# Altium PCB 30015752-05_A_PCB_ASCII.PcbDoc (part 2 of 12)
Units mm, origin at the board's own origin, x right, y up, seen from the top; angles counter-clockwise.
Board outline 100.05 x 72 mm, 10 copper layers (Top, GND_2, Signal_3, Signal_4, PWR_5, GND_6, Signal_7, Signal_8, GND_9, Bottom), stack 1.493 mm thick; 577 components, 546 nets, 2389 pads, 1412 vias.
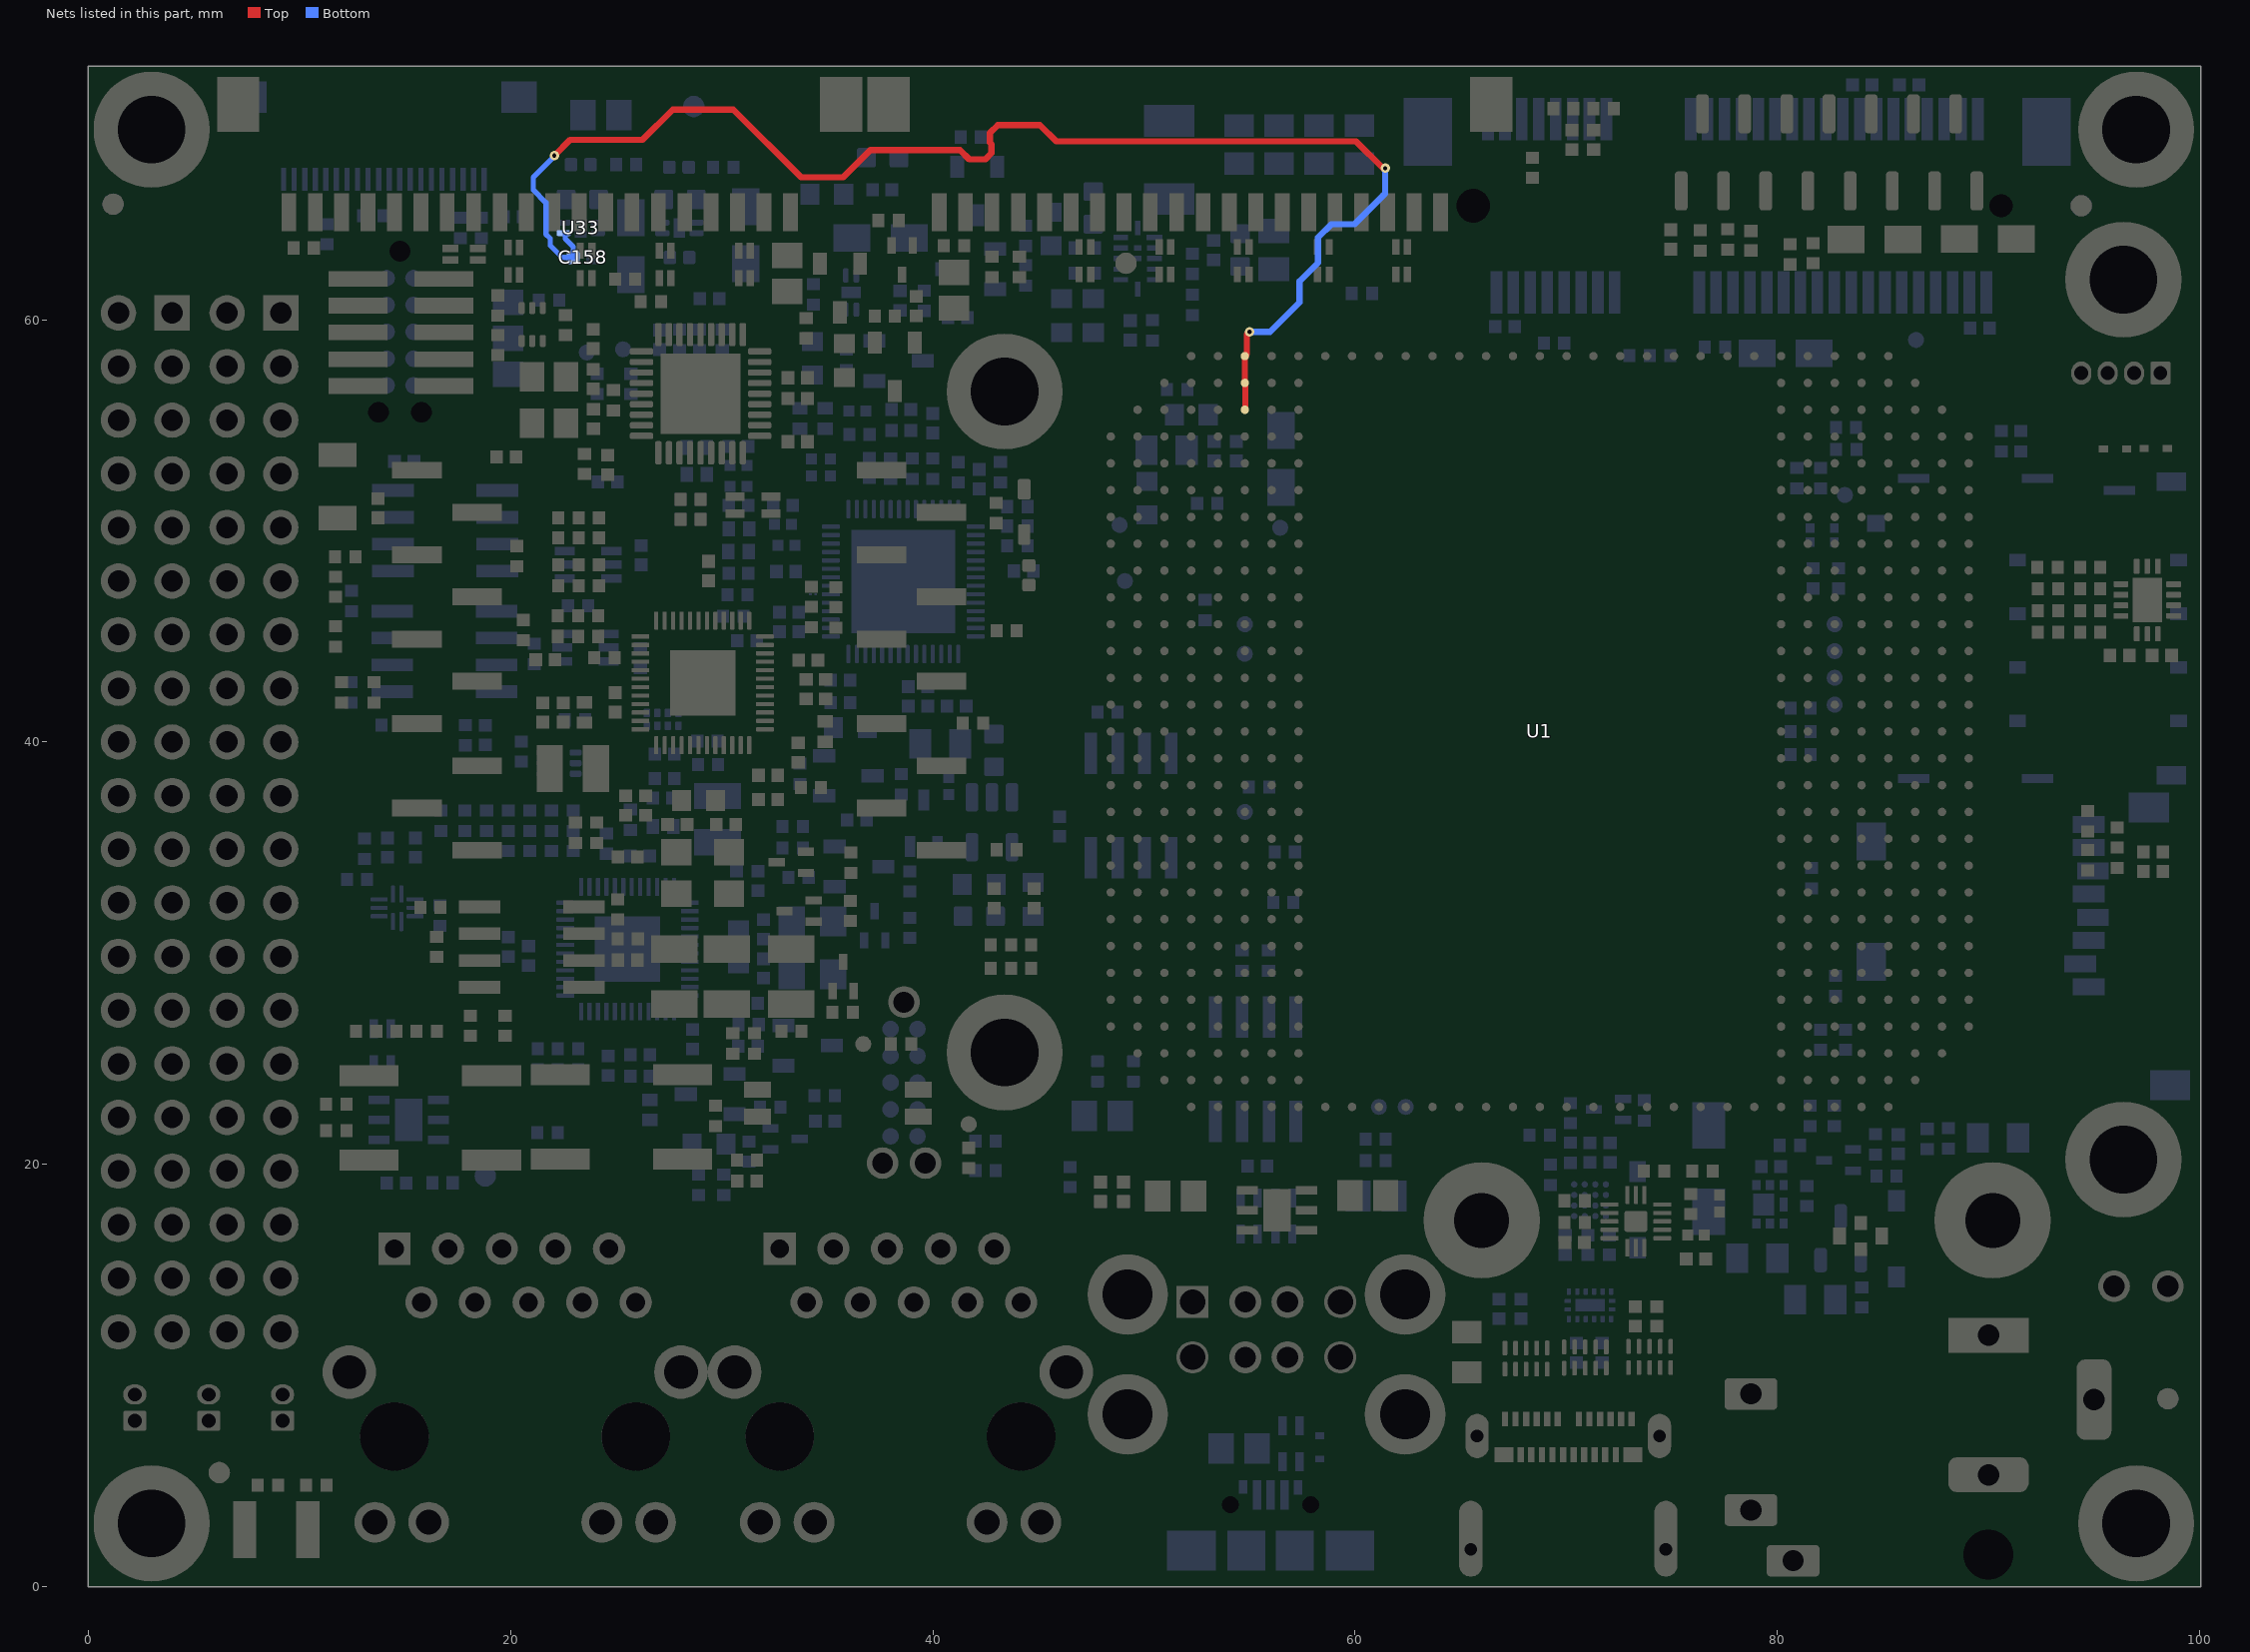
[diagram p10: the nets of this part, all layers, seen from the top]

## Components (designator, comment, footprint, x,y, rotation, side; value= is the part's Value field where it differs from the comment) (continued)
R56 "0" RESC1005X40N#1 96.1,34.52 r270 top
R57 "0" RESC1005X40N#1 96.1,35.48 r90 top
R58 "100" RESC1005X40N#1 77.05,58.7 r0 bottom
R59 "1.0K" RESC1005X40N#1 19.74,26.56 r90 top
R60 "120" RESC1005X40N#1 16.5,30.3 r270 top
R61 "1.0K" RESC1005X40N#1 12.459,46.681 r270 bottom
R62 "120" RESC1005X40N#1 14.375,40.8 r0 bottom
R63 "120" RESC1005X40N#1 12.175,48.775 r180 top
R64 "100" RESC1005X40N#1 87.1,21.2 r90 bottom
R65 "0" RESC1005X40N#1 13.075,34.95 r270 bottom
R66 "0" RESC1005X40N#1 12.725,33.5 r0 bottom
R67 "0" RESC1005X40N#1 16.7,36.275 r270 bottom
R68 "0" RESC1005X40N#1 16.65,31.775 r90 bottom
R69 "100K" RESC1005X40N#1 31.3,20.6 r90 bottom
R70 "10.0K" RESC1005X40N#1 32.3,22.7 r0 bottom
R71 "0" RESC1609X55N 29.4,20.95 r180 bottom
R72 "1.0K" RESC1005X40N#1 33.365,34.992 r0 bottom
R73 "1.0K" RESC1005X40N#1 33.365,35.992 r0 bottom
R74 "10.0K" RESC1005X40N#1 33.64,33.592 r0 bottom
R75 "10.0K" RESC1005X40N#1 24.54,35.192 r90 bottom
R76 "0" RESC1005X40N#1 13.525,42.35 r90 top
R77 "0" RESC1005X40N#1 12,42.35 r90 top
R78 "0" RESC1005X40N#1 11.75,21.6 r180 top
R79 "0" RESC1005X40N#1 11.75,22.85 r180 top
R80 "10.0K" RESC1005X40N#1 24.2,39 r270 bottom
R81 "4.7K" RESC1005X40N#1 25.675,36.325 r270 bottom
R82 "2.37K" RESC1005X40N#1 31.275,26.625 r180 bottom
R83 "150" RESC1005X40N#1 28.9,19.025 r90 bottom
R84 "150" RESC1005X40N#1 10.8,4.8 r180 top
R85 "0" RESC3225X60N 8.9,2.7 r0 top
R86 "10.0K" RESC1005X40N#1 20.915,36.272 r90 bottom
R87 "10.0K" RESC1005X40N#1 20.915,35.312 r90 bottom
R88 "10.0K" RESC1005X40N#1 19.89,36.272 r90 bottom
R89 "10.0K" RESC1005X40N#1 19.89,35.312 r90 bottom
R90 "10.0K" RESC1005X40N#1 21.76,24.475 r180 bottom
R91 "10.0K" RESC1005X40N#1 22.72,24.475 r180 bottom
R92 "10.0K" RESC1005X40N#1 21.94,36.272 r90 bottom
R93 "10.0K" RESC1005X40N#1 21.94,35.312 r90 bottom
R94 "10.0K" RESC1005X40N#1 18.865,36.272 r90 bottom
R95 "10.0K" RESC1005X40N#1 18.865,35.312 r90 bottom
R96 "10.0K" RESC1005X40N#1 22.965,36.272 r90 bottom
R97 "10.0K" RESC1005X40N#1 22.965,35.312 r90 bottom
R98 "10.0K" RESC1005X40N#1 17.84,36.272 r90 bottom
R99 "10.0K" RESC1005X40N#1 17.84,35.312 r90 bottom
R100 "10.0K" RESC1005X40N#1 21.76,25.475 r180 bottom
R101 "10.0K" RESC1005X40N#1 22.72,25.475 r180 bottom
R102 "12K" RESC1609X55N 30.8,30.3 r90 bottom
R103 "12K" RESC1609X55N 28.9,37.225 r180 top
R104 "1.0K" RESC1005X40N#1 24.075,35.7 r270 top
R105 "1.0K" RESC1005X40N#1 23.075,35.7 r270 top
R106 "10.0K" RESC1005X40N#1 29.35,38.925 r0 bottom
R107 "10.0K" RESC1005X40N#1 24.45,44 r180 top
R108 "100K" RESC1005X40N#1 36.12,34.28 r90 top
R109 "100K" RESC1005X40N#1 36.1,32 r90 top
R110 "22" RESC1005X40N#1 94.825,45.2 r180 top
R111 "22" RESC1005X40N#1 94.825,46.225 r180 top
R112 "49.9" RESC1005X40N#1 92.8,48.275 r0 top
R113 "4.7K" RESC1005X40N#1 23.05,41.05 r180 bottom
R114 "2.37K" RESC1005X40N#1 34.225,37.85 r180 top
R115 "150" RESC1005X40N#1 46.5,19.4 r90 bottom
R116 "150" RESC1005X40N#1 30.1,19.025 r90 bottom
R117 "49.9" RESC1005X40N#1 92.825,46.225 r180 top
R118 "10.0K" RESC1005X40N#1 22.745,47.4 r180 top
R119 "10.0K" RESC1005X40N#1 23.705,47.4 r180 top
R120 "10.0K" RESC1005X40N#1 22.745,48.4 r180 top
R121 "10.0K" RESC1005X40N#1 23.705,48.4 r180 top
R122 "10.0K" RESC1005X40N#1 35.4,46.855 r90 top
R123 "10.0K" RESC1005X40N#1 35.4,45.895 r90 top
R124 "10.0K" RESC1005X40N#1 22.72,45.975 r180 top
R125 "10.0K" RESC1005X40N#1 23.68,45.975 r180 top
R126 "10.0K" RESC1005X40N#1 22.745,49.675 r180 top
R127 "10.0K" RESC1005X40N#1 23.705,49.675 r180 top
R128 "10.0K" RESC1005X40N#1 22.72,45 r180 top
R129 "10.0K" RESC1005X40N#1 23.68,45 r180 top
R130 "10.0K" RESC1005X40N#1 22.745,50.625 r180 top
R131 "10.0K" RESC1005X40N#1 23.705,50.625 r180 top
R132 "10.0K" RESC1005X40N#1 34.25,46.88 r90 top
R133 "10.0K" RESC1005X40N#1 34.25,45.92 r90 top
R134 "10.0K" RESC1005X40N#1 10.2,63.4 r180 top
R135 "1M_1%" RESC1005X40N#1 24.869,56.191 r270 top
R136 "47K" RESC1005X40N#1 25.425,61.925 r0 top
R137 "10.0K" RESC1005X40N#1 26.65,60.85 r180 top
R138 "47K" RESC1005X40N#1 30.025,59.05 r90 bottom
R139 "47K" RESC1005X40N#1 28.95,59.05 r90 bottom
R140 "47K" RESC1005X40N#1 28,59.05 r90 bottom
R141 "12.1k" RESC1005X40N#1 23.5,53.175 r90 top
R142 "10.0K" RESC1005X40N#1 54.65,29.65 r90 bottom
R143 "10.0K" RESC1005X40N#1 55.9,29.65 r90 bottom
R144 "100K" RESC1005X40N#1 37.9,64.7 r0 top
R145 "10.0K" RESC1005X40N#1 37.725,60.175 r0 top
R146 "0" RESC1609X55N 35.809,58.069 r270 top
R147 "10.0K" RESC1005X40N#1 70.4,18.275 r0 top
R148 "10.0K" RESC1005X40N#1 70.4,17.25 r0 top
R149 "47K" RESC1005X40N#1 69.25,19.5 r90 bottom
R150 "52.3k" RESC1005X40N#1 68.75,21.375 r0 bottom
R151 "1.0K" RESC1005X40N#1 70.205,20.55 r270 bottom
R152 "22.1K" RESC1005X40N#1 70.2,22.425 r270 bottom
R153 "100K" RESC1005X40N#1 73.7,22.55 r90 bottom
R154 "10.0K" RESC1005X40N#1 43.2,52.78 r270 bottom
R155 "0" RESC1005X40N#1 44,50.225 r180 bottom
R156 "0" RESC1005X40N#1 44,49.3 r180 bottom
R157 "0" RESC1005X40N#1 41.2,52.775 r270 bottom
R158 "0" RESC1005X40N#1 44,51.15 r180 bottom
R159 "2.2K" RESC1005X40N#1 36.525,54.575 r180 bottom
R160 "100" RESC1005X40N#1 34.875,23.25 r0 bottom
R161 "100" RESC1005X40N#1 34,59.6 r270 top
R162 "2.2M" RESC1005X40N#1 88.1,21.225 r90 bottom
R163 "10.0K" RESC1005X40N#1 23.2,46.45 r180 bottom
R164 "0" RESC1005X40N#1 30.75,46.975 r180 bottom
R165 "0" RESC1005X40N#1 30.55,45.95 r180 bottom
R166 "100" RESC1005X40N#1 38.5,38 r90 bottom
R167 "100" RESC1005X40N#1 39.6,60.9 r270 bottom
R168 "100K" RESC1005X40N#1 38.9,31.2 r90 bottom
R169 "10.0K" RESC1005X40N#1 33.7,38.5 r270 bottom
R170 "0" RESC1609X55N 36.1,40.675 r0 bottom
R171 "2.2K" RESC1005X40N#1 82.05,25.9 r90 bottom
R172 "2.2K" RESC1005X40N#1 83.225,25.9 r90 bottom
R173 "0" RESC1005X40N#1 74.16,19.68 r180 top
R174 "0" RESC1005X40N#1 76.46,19.68 r180 top
R175 "0" RESC1005X40N#1 39.025,52.95 r270 bottom
R176 "0" RESC1005X40N#1 40,52.95 r270 bottom
R177 "0" RESC1005X40N#1 80.6,63.1 r270 top
R178 "0" RESC1005X40N#1 81.7,63.15 r270 top
R179 "2.2K" RESC1005X40N#1 11.3,64.05 r270 bottom
R180 "2.2K" RESC1005X40N#1 13.5,64.925 r0 bottom
R181 "2.2K" RESC1005X40N#1 42.8,62.5 r270 top
R182 "2.2K" RESC1005X40N#1 44.1,62.5 r270 top
R183 "2.2K" RESC1005X40N#1 76.35,63.75 r270 top
R184 "2.2K" RESC1005X40N#1 77.65,63.8 r270 top
R185 "0" RESC1005X40N#1 17.625,64.35 r90 bottom
R186 "0" RESC1005X40N#1 18.624,64.35 r90 bottom
R187 "0" RESC1005X40N#1 11.7,47.35 r270 top
R188 "0" RESC1005X40N#1 11.7,45 r270 top
R189 "0" RESC1005X40N#1 20.3,48.8 r270 top
R190 "0" RESC1005X40N#1 20.6,45.3 r270 top
R191 "0" RESC1005X40N#1 28.525,50.55 r180 top
R192 "0" RESC1005X40N#1 28.525,51.5 r180 top
R193 "10.0K" RESC1005X40N#1 35.9,58.1 r270 bottom
R194 "100K" RESC1005X40N#1 41.8,68.65 r180 bottom
R195 "49.9" RESC1005X40N#1 92.825,47.25 r0 top
R196 "0" RESC1005X40N#1 41.9,40.9 r0 top
R197 "0" RESC1005X40N#1 43.5,34.9 r0 top
R198 "10.0K" RESC1005X40N#1 43.5,45.275 r180 top
R199 "0" RESC1609X55N 34.3,58.175 r270 bottom
R203 "120" RESC1005X40N#1 31.55,25.725 r270 top
R204 "120" RESC1005X40N#1 30.525,25.725 r270 top
R205 "0" RESC1005X40N#1 53,51.3 r0 bottom
R213 "0" RESC1005X40N#1 13.155,26.3 r180 top
R214 "0.0" RESC2013X70N 65.3,11.1 r90 top
R215 "10.0K" RESC1005X40N#1 41,63.5 r180 top
R216 "100K" RESC1005X40N#1 35.73,27.2 r0 top
R217 "49.9" RESC1005X40N#1 71.772,70 r180 top
R218 "49.9" RESC1005X40N#1 69.872,70 r0 top
R219 "0" RESC1609X55N 50.15,51.55 r270 bottom
R220 "0" RESC1609X55N 52.24,55.5 r0 bottom
R221 "0" RESC1005X40N#1 52.9,46.25 r90 bottom
R222 "0" RESC1005X40N#1 83.268,53.85 r180 bottom
R223 "0" RESC1005X40N#1 83.255,54.9 r180 bottom
R224 "0" RESC1005X40N#1 82.9,47.75 r270 bottom
R225 "0" RESC1005X40N#1 81.7,47.75 r270 bottom
R226 "0" RESC1005X40N#1 80.925,52.5 r270 bottom
R227 "0" RESC1005X40N#1 82.05,52.5 r270 bottom
R228 "0" RESC1005X40N#1 28.525,50.55 r180 bottom
R229 "0" RESC1005X40N#1 28.525,51.5 r180 bottom
R230 "0" RESC1005X40N#1 73.48,58.3 r0 bottom
R231 "0" RESC1005X40N#1 74.44,58.3 r0 bottom
R232 "0" RESC1005X40N#1 82.7,22.3 r90 bottom
R233 "0" RESC1005X40N#1 16.775,19.125 r180 bottom
R234 "0" RESC1005X40N#1 75.9,18.12 r270 top
R235 "10.0K" RESC1005X40N#1 48.275,41.425 r180 bottom
R236 "22" RESC1005X40N#1 94.825,48.275 r180 top
R237 "22" RESC1005X40N#1 94.825,47.25 r180 top
R238 "0" RESC1005X40N#1 90.605,54.25 r270 bottom
R239 "0" RESC1005X40N#1 91.525,54.25 r270 bottom
R240 "0" RESC1005X40N#1 25.7,56.96 r270 bottom
R241 "0" RESC1005X40N#1 24.1,56.96 r270 bottom
R242 "0" RESC1005X40N#1 60.975,21.2 r0 bottom
R243 "0" RESC1005X40N#1 60.975,20.175 r0 bottom
R244 "10.0K" RESC1005X40N#1 29.325,40.05 r180 bottom
R245 "0" RESC1005X40N#1 25.075,32.075 r270 top
R246 "0" RESC1005X40N#1 25.55,30.675 r180 top
R247 "0" RESC1005X40N#1 16.2,32.175 r180 top
R248 "0" RESC1005X40N#1 17.85,40.325 r90 bottom
R249 "0" RESC1005X40N#1 21.125,44.175 r90 bottom
R250 "0" RESC1005X40N#1 12.45,42.35 r270 bottom
R251 "10.0K" RESC1005X40N#1 19.4,58.8 r90 top
R252 "0" RESC1005X40N#1 19.4,60.675 r90 top
R253 "10.0K" RESC1005X40N#1 21.825,60.925 r0 bottom
R254 "0" RESC1005X40N#1 22.6,59.75 r270 top
R255 "0.0" RESC2013X70N 90.45,21.25 r0 bottom
R256 "0" RESC1005X40N#1 51.575,56.7 r180 bottom
R257 "0" RESC1005X40N#1 60.325,61.25 r180 bottom
R258 "47k" RESC1005X40N#1 43,50.85 r270 top
R259 "100K" RESC1005X40N#2 49.5,24.4 r90 bottom
R260 "100K" RESC1005X40N#2 47.8,24.4 r90 bottom
S2 "TDA02H0SB1" SW_TDA02 35.5,22.9 r180 top
SW1 "KSC221JLFS" SW_KSC221J 16.2,22.2 r270 top locked
SW2 "KSC221JLFS" SW_KSC221J 25.25,22.25 r270 top locked
TP1 "TESTPOINT" TP0762 61.13,22.72 r90 bottom
TP2 "TESTPOINT" TP0762 62.4,22.72 r90 bottom
TP3 "TESTPOINT" TP0762 56.45,50.15 r90 bottom
TP4 "TESTPOINT" TP0762 54.78,45.58 r90 bottom
TP5 "TESTPOINT" TP0762 54.775,44.175 r90 bottom
TP6 "TESTPOINT" TP0762 48.85,50.275 r90 bottom
TP7 "TESTPOINT" TP0762 49.1,47.625 r90 bottom
TP8 "TESTPOINT" TP0762 86.575,59.048 r90 bottom
TP9 "TESTPOINT" TP0762 83.2,51.7 r90 bottom
TP10 "TESTPOINT" TP0762 54.78,36.69 r90 bottom
TP13 "TESTPOINT" TP0762 41.7,21.9 r90 top
TP14 "TESTPOINT" TP0762 36.7,25.7 r90 top
TP15 "TESTPOINT" TP0762 23.61,58.45 r90 bottom
TP16 "TESTPOINT" TP0762 25.325,58.6 r90 bottom
TP18 "TESTPOINT" TP0762 82.72,41.77 r90 bottom
TP19 "TESTPOINT" TP0762 82.72,43.04 r90 bottom
TP20 "TESTPOINT" TP0762 82.72,44.31 r90 bottom
TP21 "TESTPOINT" TP0762 82.72,45.58 r90 bottom
U1 "CCWi-i.MX8X" CC8X_LGA 68.75,40.5 r270 top locked
U2 "SIP32401A" SON50P120X160X60-5T55X91N 36.125,61.29 r270 bottom
U3 "MP2316" QFN_MPS_MP2316 49.7,62.9 r180 bottom
U4 "NLASB3157DFT2G" SOT65P210X110-6N 23.55,44.475 r0 bottom
U5 "NLASB3157DFT2G" SOT65P210X110-6N 23.675,48.4 r0 bottom
U6 "TCAN1042HGVDR" SOIC127P600X175-8N 21,30.3 r180 top
U7 "TCAN1042HGVDR" SOIC127P600X175-8N 16.859,44.281 r180 bottom
U8 "LTC2862IS8-2#PBF" SOIC127P600X175-8N 16.9,50 r180 bottom locked
U9 "DMG1026UV-7" SOTFL50P160X60-6N 22.3,39 r180 bottom
U10 "SN74AVC2T245" QFN40P180X140X55-10N 14.625,32.15 r90 bottom
U11 "AR8031" QFN40P600X600X80-49T380N 25.54,30.192 r180 bottom
U12 "AR8031" QFN40P600X600X80-49T380N 29.1,42.8 r90 top locked
U13 "USB2514BI-AEZG" QFN50P600X600X100-37AN 29,56.5 r90 top locked
U14 "MIC2026" SOIC127P600X175-8N 55.3,24.5 r270 bottom
U15 "TPD4E001DRSR" SON95P300X300X80-7N 56.3,17.825 r270 top
U16 "TPD4E001DRSR" SON95P300X300X80-7N 15.175,22.1 r270 bottom
U17 "CBTU02043" PQFN40P160X240X55-17T140X60N 71.125,13.325 r90 bottom
U18 "PTN5110" QFN40P260X260X40-17T100X110N 73.3,17.3 r180 top
U19 "NX5P3290" BGA16N50P4X4_205X205X59B32N 71.13,18.3 r180 bottom
U20 "MAX98089" QFN40P700X700X80-57T560X560N 38.6,47.6 r180 bottom locked
U21 "SI2323DS-T1-E3" SOT95P240X110_GSD-3N 38.375,58.05 r90 bottom
U22 "DMG1026UV-7" SOTFL50P160X60-6N 21.025,59.775 r90 top
U23 "SI2323DS-T1-E3" SOT95P240X110_GSD-3N 29.45,23.325 r270 bottom
U24 "SI2323DS-T1-E3" SOT95P240X110_GSD-3N 38.2,57.775 r180 top
U25 "SI2323DS-T1-E3" SOT95P240X110_GSD-3N 36,38.4 r90 bottom
U26 "FDMA908PZ" FAIRCHILD_MICROFET_2X2 79.65,18.1 r270 bottom
U27 "AP2202" SOT95P280X145-5N 42.8,36.2 r270 bottom
U28 "AB-557-03-HCHC-F-L-C" QFN50P320X250X90-15T140X210N 97.525,46.725 r180 top
U29 "NTS0102GT" PSON50P195X100X50-8N 27.2,41.075 r270 bottom
U31 "MIC2026" SOIC127P600X175-8N 49.4,37 r270 bottom
U32 "SIP32401A" SON50P120X160X60-5T55X91N 28,64.35 r180 bottom
U33 "SIP32401A" SON50P120X160X60-5T55X91N 23.325,64.35 r180 bottom
X1 "RH100-25.000-20-EXT-TR" OSC210P320X250X90-4N 34.3,30.25 r180 bottom
X2 "RH100-25.000-20-EXT-TR" OSC210P320X250X90-4N 29.1,33.8 r90 top
X3 "24MHz" XTAL_C3E-3427 21.819,56.191 r90 top

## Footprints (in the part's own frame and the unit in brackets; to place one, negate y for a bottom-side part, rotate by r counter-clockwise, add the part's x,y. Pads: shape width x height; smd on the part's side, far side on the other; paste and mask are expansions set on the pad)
BGA16N50P4X4_205X205X59B32N [mm] "Ball Grid Array (BGA), 0.50 mm pitch, square; 16 pin, 2.05 mm L X 2.05 mm W X 0.595 mm H body"
  round 0.3 smd mask+0: A1(-0.75,0.75) A2(-0.25,0.75) A3(0.25,0.75) A4(0.75,0.75) B1(-0.75,0.25) B2(-0.25,0.25) B3(0.25,0.25) B4(0.75,0.25) C1(-0.75,-0.25) C2(-0.25,-0.25) C3(0.25,-0.25) C4(0.75,-0.25) D1(-0.75,-0.75) D2(-0.25,-0.75) D3(0.25,-0.75) D4(0.75,-0.75)
CAPC0603X33N [mm]
  rect 0.46x0.42 smd: 1(-0.33,0) 2(0.33,0)
CAPC1005X55L [mm]
  rect 0.52x0.52 smd mask+0: 1(-0.4,0) 2(0.4,0)
CAPC1005X55N#1 [mm]
  rect 0.6x0.62 smd mask+0: 1(-0.46,0) 2(0.46,0)
CAPC1005X55N#2 [mm]
  rrect30% 0.6x0.62 smd mask+0: 1(-0.46,0) 2(0.46,0)
CAPC1608X90N [mm] "0603"
  rrect22% 0.89x0.93 smd: 1(-0.77,0) 2(0.77,0)
CAPC2013X135N [mm] "0805, 1.35mm max height"
  rect 1.05x1.4 smd: 1(-0.9,0) 2(0.9,0)
CAPC2013X145N [mm] "0805, 1.45mm max height"
  rect 1.15x1.45 smd: 1(-0.9,0) 2(0.9,0)
CAPC3216X190N [mm]
  rect 1.15x1.8 smd: 1(-1.5,0) 2(1.5,0)
CAPMP3216X120N [mm]
  rect 1.75x1.3 smd: 1(-1.35,0) 2(1.35,0)
CC8X_LGA [mm]
  round 0.4 smd mask+0: A4(-13.97,20.32) A5(-12.7,20.32) A6(-11.43,20.32) A7(-10.16,20.32) A8(-8.89,20.32) A9(-7.62,20.32) A10(-6.35,20.32) A11(-5.08,20.32) A12(-3.81,20.32) A13(-2.54,20.32) A14(-1.27,20.32) A15(0,20.32) A16(1.27,20.32) A17(2.54,20.32) A18(3.81,20.32) A19(5.08,20.32) A20(6.35,20.32) A21(7.62,20.32) A22(8.89,20.32) A23(10.16,20.32) A24(11.43,20.32) A25(12.7,20.32) A26(13.97,20.32) AA1(-17.78,-5.08) AA29(17.78,-5.08) AB1(-17.78,-6.35) AB29(17.78,-6.35) AC1(-17.78,-7.62) AC29(17.78,-7.62) AD1(-17.78,-8.89) AD29(17.78,-8.89) AE1(-17.78,-10.16) AE29(17.78,-10.16) AF1(-17.78,-11.43) AF2(-16.51,-11.43) AF3(-15.24,-11.43) AF4(-13.97,-11.43) AF5(-12.7,-11.43) AF6(-11.43,-11.43) AF7(-10.16,-11.43) AF8(-8.89,-11.43) AF9(-7.62,-11.43) AF10(-6.35,-11.43) AF11(-5.08,-11.43) AF12(-3.81,-11.43) AF13(-2.54,-11.43) AF14(-1.27,-11.43) AF15(0,-11.43) AF16(1.27,-11.43) AF17(2.54,-11.43) AF18(3.81,-11.43) AF19(5.08,-11.43) AF20(6.35,-11.43) AF21(7.62,-11.43) AF22(8.89,-11.43) AF23(10.16,-11.43) AF24(11.43,-11.43) AF25(12.7,-11.43) AF26(13.97,-11.43) AF27(15.24,-11.43) AF28(16.51,-11.43) AF29(17.78,-11.43) AG1(-17.78,-12.7) AG2(-16.51,-12.7) AG3(-15.24,-12.7) AG4(-13.97,-12.7) AG5(-12.7,-12.7) AG6(-11.43,-12.7) AG7(-10.16,-12.7) AG8(-8.89,-12.7) AG9(-7.62,-12.7) AG10(-6.35,-12.7) AG11(-5.08,-12.7) AG12(-3.81,-12.7) AG13(-2.54,-12.7) AG14(-1.27,-12.7) AG15(0,-12.7) AG16(1.27,-12.7) AG17(2.54,-12.7) AG18(3.81,-12.7) AG19(5.08,-12.7) AG20(6.35,-12.7) AG21(7.62,-12.7) AG22(8.89,-12.7) AG23(10.16,-12.7) AG24(11.43,-12.7) AG25(12.7,-12.7) AG26(13.97,-12.7) AG27(15.24,-12.7) AG28(16.51,-12.7) AG29(17.78,-12.7) AH1(-17.78,-13.97) AH2(-16.51,-13.97) AH3(-15.24,-13.97) AH4(-13.97,-13.97) AH5(-12.7,-13.97) AH6(-11.43,-13.97) AH7(-10.16,-13.97) AH8(-8.89,-13.97) AH9(-7.62,-13.97) AH10(-6.35,-13.97) AH11(-5.08,-13.97) AH12(-3.81,-13.97) AH13(-2.54,-13.97) AH14(-1.27,-13.97) AH15(0,-13.97) AH16(1.27,-13.97) AH17(2.54,-13.97) AH18(3.81,-13.97) AH19(5.08,-13.97) AH20(6.35,-13.97) AH21(7.62,-13.97) AH22(8.89,-13.97) AH23(10.16,-13.97) AH24(11.43,-13.97) AH25(12.7,-13.97) AH26(13.97,-13.97) AH27(15.24,-13.97) AH28(16.51,-13.97) AH29(17.78,-13.97) AJ1(-17.78,-15.24) AJ2(-16.51,-15.24) AJ3(-15.24,-15.24) AJ4(-13.97,-15.24) AJ5(-12.7,-15.24) AJ6(-11.43,-15.24) AJ7(-10.16,-15.24) AJ8(-8.89,-15.24) AJ9(-7.62,-15.24) AJ10(-6.35,-15.24) AJ11(-5.08,-15.24) AJ12(-3.81,-15.24) AJ13(-2.54,-15.24) AJ14(-1.27,-15.24) AJ15(0,-15.24) AJ16(1.27,-15.24) AJ17(2.54,-15.24) AJ18(3.81,-15.24) AJ19(5.08,-15.24) AJ20(6.35,-15.24) AJ21(7.62,-15.24) AJ22(8.89,-15.24) AJ23(10.16,-15.24) AJ24(11.43,-15.24) AJ25(12.7,-15.24) AJ26(13.97,-15.24) AJ27(15.24,-15.24) AJ28(16.51,-15.24) AJ29(17.78,-15.24) AK1(-17.78,-16.51) AK2(-16.51,-16.51) AK3(-15.24,-16.51) AK4(-13.97,-16.51) AK5(-12.7,-16.51) AK6(-11.43,-16.51) AK7(-10.16,-16.51) AK8(-8.89,-16.51) AK9(-7.62,-16.51) AK10(-6.35,-16.51) AK11(-5.08,-16.51) AK12(-3.81,-16.51) AK13(-2.54,-16.51) AK14(-1.27,-16.51) AK15(0,-16.51) AK16(1.27,-16.51) AK17(2.54,-16.51) AK18(3.81,-16.51) AK19(5.08,-16.51) AK20(6.35,-16.51) AK21(7.62,-16.51) AK22(8.89,-16.51) AK23(10.16,-16.51) AK24(11.43,-16.51) AK25(12.7,-16.51) AK26(13.97,-16.51) AK27(15.24,-16.51) AK28(16.51,-16.51) AK29(17.78,-16.51) AL2(-16.51,-17.78) AL3(-15.24,-17.78) AL4(-13.97,-17.78) AL5(-12.7,-17.78) AL6(-11.43,-17.78) AL7(-10.16,-17.78) AL8(-8.89,-17.78) AL9(-7.62,-17.78) AL10(-6.35,-17.78) AL11(-5.08,-17.78) AL12(-3.81,-17.78) AL13(-2.54,-17.78) AL14(-1.27,-17.78) AL15(0,-17.78) AL16(1.27,-17.78) AL17(2.54,-17.78) AL18(3.81,-17.78) AL19(5.08,-17.78) AL20(6.35,-17.78) AL21(7.62,-17.78) AL22(8.89,-17.78) AL23(10.16,-17.78) AL24(11.43,-17.78) AL25(12.7,-17.78) AL26(13.97,-17.78) AL27(15.24,-17.78) AL28(16.51,-17.78) AM3(-15.24,-19.05) AM4(-13.97,-19.05) AM5(-12.7,-19.05) AM6(-11.43,-19.05) AM7(-10.16,-19.05) AM8(-8.89,-19.05) AM9(-7.62,-19.05) AM10(-6.35,-19.05) AM11(-5.08,-19.05) AM12(-3.81,-19.05) AM13(-2.54,-19.05) AM14(-1.27,-19.05) AM15(0,-19.05) AM16(1.27,-19.05) AM17(2.54,-19.05) AM18(3.81,-19.05) AM19(5.08,-19.05) AM20(6.35,-19.05) AM21(7.62,-19.05) AM22(8.89,-19.05) AM23(10.16,-19.05) AM24(11.43,-19.05) AM25(12.7,-19.05) AM26(13.97,-19.05) AM27(15.24,-19.05) AN4(-13.97,-20.32) AN5(-12.7,-20.32) AN6(-11.43,-20.32) AN7(-10.16,-20.32) AN8(-8.89,-20.32) AN9(-7.62,-20.32) AN10(-6.35,-20.32) AN11(-5.08,-20.32) AN12(-3.81,-20.32) AN13(-2.54,-20.32) AN14(-1.27,-20.32) AN15(0,-20.32) AN16(1.27,-20.32) AN17(2.54,-20.32) AN18(3.81,-20.32) AN19(5.08,-20.32) AN20(6.35,-20.32) AN21(7.62,-20.32) AN22(8.89,-20.32) AN23(10.16,-20.32) AN24(11.43,-20.32) AN25(12.7,-20.32) AN26(13.97,-20.32) B3(-15.24,19.05) B4(-13.97,19.05) B5(-12.7,19.05) B6(-11.43,19.05) B7(-10.16,19.05) B8(-8.89,19.05) B9(-7.62,19.05) B10(-6.35,19.05) B11(-5.08,19.05) B12(-3.81,19.05) B13(-2.54,19.05) B14(-1.27,19.05) B15(0,19.05) B16(1.27,19.05) B17(2.54,19.05) B18(3.81,19.05) B19(5.08,19.05) B20(6.35,19.05) B21(7.62,19.05) B22(8.89,19.05) B23(10.16,19.05) B24(11.43,19.05) B25(12.7,19.05) B26(13.97,19.05) B27(15.24,19.05) C2(-16.51,17.78) C3(-15.24,17.78) C4(-13.97,17.78) C5(-12.7,17.78) C6(-11.43,17.78) C7(-10.16,17.78) C8(-8.89,17.78) C9(-7.62,17.78) C10(-6.35,17.78) C11(-5.08,17.78) C12(-3.81,17.78) C13(-2.54,17.78) C14(-1.27,17.78) C15(0,17.78) C16(1.27,17.78) C17(2.54,17.78) C18(3.81,17.78) C19(5.08,17.78) C20(6.35,17.78) C21(7.62,17.78) C22(8.89,17.78) C23(10.16,17.78) C24(11.43,17.78) C25(12.7,17.78) C26(13.97,17.78) C27(15.24,17.78) C28(16.51,17.78) D1(-17.78,16.51) D2(-16.51,16.51) D3(-15.24,16.51) D4(-13.97,16.51) D5(-12.7,16.51) D6(-11.43,16.51) D7(-10.16,16.51) D8(-8.89,16.51) D9(-7.62,16.51) D10(-6.35,16.51) D11(-5.08,16.51) D12(-3.81,16.51) D13(-2.54,16.51) D14(-1.27,16.51) D15(0,16.51) D16(1.27,16.51) D17(2.54,16.51) D18(3.81,16.51) D19(5.08,16.51) D20(6.35,16.51) D21(7.62,16.51) D22(8.89,16.51) D23(10.16,16.51) D24(11.43,16.51) D25(12.7,16.51) D26(13.97,16.51) D27(15.24,16.51) D28(16.51,16.51) D29(17.78,16.51) E1(-17.78,15.24) E2(-16.51,15.24) E3(-15.24,15.24) E4(-13.97,15.24) E5(-12.7,15.24) E6(-11.43,15.24) E7(-10.16,15.24) E8(-8.89,15.24) E9(-7.62,15.24) E10(-6.35,15.24) E11(-5.08,15.24) E12(-3.81,15.24) E13(-2.54,15.24) E14(-1.27,15.24) E15(0,15.24) E16(1.27,15.24) E17(2.54,15.24) E18(3.81,15.24) E19(5.08,15.24) E20(6.35,15.24) E21(7.62,15.24) E22(8.89,15.24) E23(10.16,15.24) E24(11.43,15.24) E25(12.7,15.24) E26(13.97,15.24) E27(15.24,15.24) E28(16.51,15.24) E29(17.78,15.24) F1(-17.78,13.97) F2(-16.51,13.97) F3(-15.24,13.97) F4(-13.97,13.97) F5(-12.7,13.97) F6(-11.43,13.97) F7(-10.16,13.97) F8(-8.89,13.97) F9(-7.62,13.97) F10(-6.35,13.97) F11(-5.08,13.97) F12(-3.81,13.97) F13(-2.54,13.97) F14(-1.27,13.97) F15(0,13.97) F16(1.27,13.97) F17(2.54,13.97) F18(3.81,13.97) F19(5.08,13.97) F20(6.35,13.97) F21(7.62,13.97) F22(8.89,13.97) F23(10.16,13.97) F24(11.43,13.97) F25(12.7,13.97) F26(13.97,13.97) F27(15.24,13.97) F28(16.51,13.97) F29(17.78,13.97) G1(-17.78,12.7) G2(-16.51,12.7) G3(-15.24,12.7) G4(-13.97,12.7) G5(-12.7,12.7) G6(-11.43,12.7) G7(-10.16,12.7) G8(-8.89,12.7) G9(-7.62,12.7) G10(-6.35,12.7) G11(-5.08,12.7) G12(-3.81,12.7) G13(-2.54,12.7) G14(-1.27,12.7) G15(0,12.7) G16(1.27,12.7) G17(2.54,12.7) G18(3.81,12.7) G19(5.08,12.7) G20(6.35,12.7) G21(7.62,12.7) G22(8.89,12.7) G23(10.16,12.7) G24(11.43,12.7) G25(12.7,12.7) G26(13.97,12.7) G27(15.24,12.7) G28(16.51,12.7) G29(17.78,12.7) H1(-17.78,11.43) H2(-16.51,11.43) H3(-15.24,11.43) H4(-13.97,11.43) H5(-12.7,11.43) H6(-11.43,11.43) H7(-10.16,11.43) H8(-8.89,11.43) H9(-7.62,11.43) H10(-6.35,11.43) H11(-5.08,11.43) H12(-3.81,11.43) H13(-2.54,11.43) H14(-1.27,11.43) H15(0,11.43) H16(1.27,11.43) H17(2.54,11.43) H18(3.81,11.43) H19(5.08,11.43) H20(6.35,11.43) H21(7.62,11.43) H22(8.89,11.43) H23(10.16,11.43) H24(11.43,11.43) H25(12.7,11.43) H26(13.97,11.43) H27(15.24,11.43) H28(16.51,11.43) H29(17.78,11.43) J1(-17.78,10.16) J29(17.78,10.16) K1(-17.78,8.89) K29(17.78,8.89) L1(-17.78,7.62) L29(17.78,7.62) M1(-17.78,6.35) M29(17.78,6.35) N1(-17.78,5.08) N29(17.78,5.08) P1(-17.78,3.81) P29(17.78,3.81) R1(-17.78,2.54) R29(17.78,2.54) T1(-17.78,1.27) T29(17.78,1.27) U1(-17.78,0) U29(17.78,0) V1(-17.78,-1.27) V29(17.78,-1.27) W1(-17.78,-2.54) W29(17.78,-2.54) Y1(-17.78,-3.81) Y29(17.78,-3.81)
conn_CSCD443CCS011B00G [mil] "Bobbintron : CSCD443CCS011B00G"
  rect 65x150 hole 40 slot 126 at 90 deg: 1(0,0)
  rrect50% 65x150 / inner rect 65x150 / far side rrect50% 65x150 hole 40 slot 126 at 90 deg: 2(-260,0)
  rrect50% 150x65 / inner rect 150x65 / far side rrect50% 150x65 hole 40 slot 126 at 0 deg: 3(-120,-197.01)
  round 0 hole 93 unplated: 4(-409,0)
CUI_SJ1-3533N [mm] "CON PWR JCK STEREO 3.5MM R/A 3.05mm"
  rrect25% 1.5x2.5 hole 1 slot 2 at 90 deg: 1(0,0) 2(2.4,2) 3(7.9,2)
DIOM5127X229AN [mm]
  rect 2.2x1.55 smd: A(2.05,0) K(-2.05,0)
  silkscreen extent -3.45,1.33 -3.15,1.63
FAIRCHILD_MICROFET_2X2 [mm]
  rect 0.47x0.4 smd mask+0: 1(-0.91,0.65) 2(-0.91,0) 3(-0.91,-0.65) 4(0.91,-0.65) 5(0.91,0) 6(0.91,0.65)
  rect 1.05x1 smd mask+0: 7(0,0.3)
  rect 0.66x0.4 smd mask+0: 8(0,-0.65)
FCI_SFW15S-2STE1LF [mm] "CONN FFC FPC VERT 15POS 1MM SMD"
  rrect50% 0.6x1.85 smd: 1(-7,-1.825) 2(-6,1.825) 3(-5,-1.825) 4(-4,1.825) 5(-3,-1.825) 6(-2,1.825) 7(-1,-1.825) 8(0,1.825) 9(1,-1.825) 10(2,1.825) 11(3,-1.825) 12(4,1.825) 13(5,-1.825) 14(6,1.825) 15(7,-1.825)
fiducial_40mil_round [mil]
  round 40 smd paste-40 mask+0: 1(0,0)
FIL_DLP11S [mm]
  rect 0.75x0.35 smd: 1(-0.65,-0.275) 2(0.65,-0.275) 3(0.65,0.275) 4(-0.65,0.275)
FIL_DLW21H [mm]
  rect 0.9x0.4 smd: 1(-0.85,-0.4) 2(0.85,-0.4) 3(0.85,0.4) 4(-0.85,0.4)
FIL_NFM21P [mm]
  rect 0.6x0.8 smd: 1(-1,0) 3(1,0)
  rect 0.6x0.65 smd: 2(0,0.625) 2(0,-0.625)
  silkscreen extent -2.05,-0.8 1.15,0.8
FOXCONN_AS0B221-S68Q-7H [mm]
  rect 0.55x2 smd: 1(0.7,-4.1) 2(1.1,4.1) 3(1.5,-4.1) 4(1.9,4.1) 5(2.3,-4.1) 6(2.7,4.1) 7(3.1,-4.1) 8(3.5,4.1) 9(3.9,-4.1) 10(4.3,4.1) 11(4.7,-4.1) 12(5.1,4.1) 13(5.5,-4.1) 14(5.9,4.1) 15(6.3,-4.1) 16(6.7,4.1) 17(10.3,-4.1) 18(10.7,4.1) 19(11.1,-4.1) 20(11.5,4.1) 21(11.9,-4.1) 22(12.3,4.1) 23(12.7,-4.1) 24(13.1,4.1) 25(13.5,-4.1) 26(13.9,4.1) 27(14.3,-4.1) 28(14.7,4.1) 29(15.1,-4.1) 30(15.5,4.1) 31(15.9,-4.1) 32(16.3,4.1) 33(16.7,-4.1) 34(17.1,4.1) 35(17.5,-4.1) 36(17.9,4.1) 37(18.3,-4.1) 38(18.7,4.1) 39(19.1,-4.1) 40(19.5,4.1) 41(19.9,-4.1) 42(20.3,4.1) 43(20.7,-4.1) 44(21.1,4.1) 45(21.5,-4.1) 46(21.9,4.1) 47(22.3,-4.1) 48(22.7,4.1) 49(23.1,-4.1) 50(23.5,4.1) 51(23.9,-4.1) 52(24.3,4.1)
  round 0 hole 1.6 unplated: H1(0,0)
  round 0 hole 1.1 unplated: H2(25,0)
  rect 2.3x3.2 smd: MT1(-2.15,-3.5) MT2(27.15,-3.5)
HIROSE_DF14A-20P-1.25H [mm]
  rect 0.7x1.8 smd: 1(11.875,-2.55) 2(10.625,-2.55) 3(9.375,-2.55) 4(8.125,-2.55) 5(6.875,-2.55) 6(5.625,-2.55) 7(4.375,-2.55) 8(3.125,-2.55) 9(1.875,-2.55) 10(0.625,-2.55) 11(-0.625,-2.55) 12(-1.875,-2.55) 13(-3.125,-2.55) 14(-4.375,-2.55) 15(-5.625,-2.55) 16(-6.875,-2.55) 17(-8.125,-2.55) 18(-9.375,-2.55) 19(-10.625,-2.55) 20(-11.875,-2.55)
  rect 2x2.6 smd: MT1(14.275,2.55) MT21(-14.275,2.55)
INDC1005X60N [mm]
  rect 0.59x0.72 smd: 1(-0.48,0) 2(0.48,0)
INDC2013X110N [mm]
  rect 1.2x1.45 smd: 1(-0.85,0) 2(0.85,0)
INDC2520X100L60N [mm] "Inductor, Chip; 2.50 mm L X 2.00 mm W X 1.00 mm H body"
  rect 1.24x2.22 smd: 1(-1.09,0) 2(1.09,0)
INDM_SRP4020TA [mm]
  rect 1.5x2.4 smd: 1(-1.85,0) 2(1.85,0)
KYCON_KMMX-ABSMT5 [mm]
  rect 0.4x0.7 smd mask+0: 1(-1.3,3)
  rect 0.4x1.4 smd: 2(-0.65,2.65) 3(0,2.65) 4(0.65,2.65)
  rect 0.4x0.65 smd mask+0: 5(1.3,3.025)
  rect 2.3x1.9 smd: 6(-3.75,0) 9(3.75,0)
  rect 1.8x1.9 smd: 7(-1.15,0) 8(1.15,0)
  round 0 hole 0.813 unplated: 10(-1.9,2.18) 11(1.9,2.18)
KYCON_KUSBX-AS2N_Flex [mm]
  rect 1.524x1.524 hole 1.2: A1(0,0)
  round 1.524 hole 1: A2(2.5,0) A3(4.5,0) B2(2.5,-2.62) B3(4.5,-2.62)
  round 1.524 hole 1.2: A4(7,0) B1(0,-2.62) B4(7,-2.62)
  round 3.81 hole 2.362: SH1(-3.07,-5.33) SH2(-3.07,0.35) SH3(10.07,-5.33) SH4(10.07,0.35)
  silkscreen extent -0.18,1.97 0.18,2.33
LEDM3020X130N [mm]
  rect 1.3x2.2 smd: A(-1.3,0) K(1.3,0)
MH_185_125_NP [mm]
  round 3.175 hole 3.175 unplated: 1(0,0)
  Keep-Out Layer circle w0.102: c0,0 r2.349
"MILLMAX_ 802-10-040-62-001000" [mil]
  rect 66x66 hole 40 mask+0: 1(100,0)
  round 66 hole 40 mask+0: 2(0,0) 3(100,-100) 4(0,-100) 5(100,-200) 6(0,-200) 7(100,-300) 8(0,-300) 9(100,-400) 10(0,-400) 11(100,-500) 12(0,-500) 13(100,-600) 14(0,-600) 15(100,-700) 16(0,-700) 17(100,-800) 18(0,-800) 19(100,-900) 20(0,-900) 21(100,-1000) 22(0,-1000) 23(100,-1100) 24(0,-1100) 25(100,-1200) 26(0,-1200) 27(100,-1300) 28(0,-1300) 29(100,-1400) 30(0,-1400) 31(100,-1500) 32(0,-1500) 33(100,-1600) 34(0,-1600) 35(100,-1700) 36(0,-1700) 37(100,-1800) 38(0,-1800) 39(100,-1900) 40(0,-1900)
MOLEX_53047-0210 [mm]
  rrect20% 0.95x1.1 hole 0.65: 1(0,0)
  oval 0.95x1.1 hole 0.65: 2(1.25,0)
MOLEX_53047-0410 [mm]
  rrect20% 0.95x1.1 hole 0.65: 1(0,0)
  oval 0.95x1.1 hole 0.65: 2(1.25,0) 3(2.5,0) 4(3.75,0)
MOLEX_78727-0001 [mm]
  rect 0.8x0.6 smd: 1(0.33,4.38) 2(0.33,1.84) 3(0.33,-0.7) 4(0.33,-3.24) 5(-7.29,4.38) 6(-7.29,1.84) 7(-7.29,-0.7) 8(-7.29,-3.24)
  rect 0.85x0.8 smd: 9(-13.99,-4.98)
  rect 1.5x0.42 smd: 10(-2.47,-6.54) 12(-6.35,7.11) 13(-12.21,7.11) 14(-12.21,-7.11) 15(-6.35,-7.11)
  rect 1.4x0.87 smd: 11(0,6.95) 16(0,-6.95)
MOLEX_201267-0005 [mm]
  rect 0.3x0.7 smd mask+0: A1(-3,3.965) A2(-2.5,3.965) A3(-2,3.965) A4(-1.5,3.965) A5(-1,3.965) A6(-0.5,3.965) A7(0.5,3.965) A8(1,3.965) A9(1.5,3.965) A10(2,3.965) A11(2.5,3.965) A12(3,3.965) B2(2.25,2.265) B3(1.75,2.265) B4(1.25,2.265) B5(0.75,2.265) B6(0.25,2.265) B7(-0.25,2.265) B8(-0.75,2.265) B9(-1.25,2.265) B10(-1.75,2.265) B11(-2.25,2.265)
  rect 0.9x0.7 smd mask+0: B1(3.05,2.265) B12(-3.05,2.265)
  oval 1.1x2.1 hole 0.6 slot 1.6 at 90 deg mask+0: MT1(-4.32,3.155) MT2(4.32,3.155)
  oval 1.1x3.6 hole 0.6 slot 2.1 at 90 deg copper offset 0,0.5 mask+0: MT3(-4.62,-2.205) MT4(4.62,-2.205)
MOLEX_500873-0806 [mm]
  rect 0.8x1.5 smd: 1(0,0) 2(1.1,-0.4) 3(2.2,0) 4(3.3,0.2) 5(4.4,0) 6(5.5,0.2) 7(6.6,0) 8(7.7,0)
  rect 1.8x1.4 smd: 9(1.2,-10.3) 10(6.9,-10.3)
  rect 1.4x1.9 smd: 11(8.5,2.85) 12(-4.65,3.85)
NET_TIE_4mil [mil] "Net Tie for 4mil traces"
  rect 5x4 smd paste-5 mask+0: 1(-5,0) 2(5,0)
  Top region: -2.99,2 3.01,2 3.01,-2 -2.99,-2
omron_xf2m-2015-1a [mm]
  rect 0.25x1.1 smd: 1(-4.75,1.95) 2(-4.25,1.95) 3(-3.75,1.95) 4(-3.25,1.95) 5(-2.75,1.95) 6(-2.25,1.95) 7(-1.75,1.95) 8(-1.25,1.95) 9(-0.75,1.95) 10(-0.25,1.95) 11(0.25,1.95) 12(0.75,1.95) 13(1.25,1.95) 14(1.75,1.95) 15(2.25,1.95) 16(2.75,1.95) 17(3.25,1.95) 18(3.75,1.95) 19(4.25,1.95) 20(4.75,1.95)
  rect 1.7x1.5 smd: M1(6.4,-1.95) M2(-6.4,-1.95)
OSC210P320X250X90-4N [mm]
  rect 1.25x1.425 smd: 1(-0.975,1.25) 2(-0.975,-1.25) 3(0.975,-1.25) 4(0.975,1.25)
PQFN40P160X240X55-17T140X60N [mm] "Pullback Quad Flat No-Lead (PQFN with Tab), 0.40 mm pitch; rect., pin 1 on short dimension, 2 pin X 6 pin, 1.60 mm L X 2.40 mm W X 0.55 mm H body"
  rrect25% 0.3x0.2 smd mask+0: 1(-0.65,1) 2(-0.65,0.6) 3(-0.65,0.2) 4(-0.65,-0.2) 5(-0.65,-0.6) 6(-0.65,-1) 9(0.65,-1) 10(0.65,-0.6) 11(0.65,-0.2) 12(0.65,0.2) 13(0.65,0.6) 14(0.65,1)
  rrect25% 0.2x0.3 smd mask+0: 7(-0.2,-1.05) 8(0.2,-1.05) 15(0.2,1.05) 16(-0.2,1.05)
  rect 0.6x1.4 smd paste-1.4 mask+0: 17(0,0)
PSON50P195X100X50-8N [mm] "Pullback Small Outline No-Lead (PSON), 0.50 mm pitch; 8 pin, 1.95 mm L X 1.00 mm W X 0.50 mm H body"
  rrect25% 0.4x0.3 smd mask+0: 1(-0.3,0.75) 2(-0.3,0.25) 3(-0.3,-0.25) 4(-0.3,-0.75) 5(0.3,-0.75) 6(0.3,-0.25) 7(0.3,0.25) 8(0.3,0.75)
QFN40P180X140X55-10N [mm] "Quad Flat No-Lead (QFN), 0.40 mm pitch; rect., 2 pin X 3 pin, 1.80 mm L X 1.40 mm W X 0.55 mm H body"
  rrect50% 0.91x0.2 smd mask+0: 1(-0.65,0.2)
  rrect50% 0.81x0.2 smd mask+0: 2(-0.65,-0.2) 6(0.65,-0.2) 7(0.65,0.2)
  rrect50% 0.2x0.81 smd mask+0: 3(-0.4,-0.85) 4(0,-0.85) 5(0.4,-0.85) 8(0.4,0.85) 9(0,0.85) 10(-0.4,0.85)
  silkscreen extent -1.35,0.5 -1.15,0.7
QFN40P260X260X40-17T100X110N [mm] "Quad Flat No-Lead (QFN with Tab), 0.40 mm pitch; square, 5 pin X 3 pin, 2.60 mm L X 2.60 mm W X 0.40 mm H body"
  rrect25% 0.84x0.2 smd mask+0: 1(-1.25,0.8) 2(-1.25,0.4) 3(-1.25,0) 4(-1.25,-0.4) 5(-1.25,-0.8) 9(1.25,-0.8) 10(1.25,-0.4) 11(1.25,0) 12(1.25,0.4) 13(1.25,0.8)
  rrect25% 0.2x0.84 smd mask+0: 6(-0.4,-1.25) 7(0,-1.25) 8(0.4,-1.25) 14(0.4,1.25) 15(0,1.25) 16(-0.4,1.25)
  rrect25% 1.1x1 smd paste-0.153 mask+0: 17(0,0)
QFN40P600X600X80-49T380N [mm] "Quad Flat No-Lead (QFN with Tab), 0.40 mm pitch; square, 12 pin X 12 pin, 6.00 mm L X 6.00 mm W X 0.80 mm H body"
  rrect25% 0.84x0.2 smd mask+0: 1(-2.95,2.2) 2(-2.95,1.8) 3(-2.95,1.4) 4(-2.95,1) 5(-2.95,0.6) 6(-2.95,0.2) 7(-2.95,-0.2) 8(-2.95,-0.6) 9(-2.95,-1) 10(-2.95,-1.4) 11(-2.95,-1.8) 12(-2.95,-2.2) 25(2.95,-2.2) 26(2.95,-1.8) 27(2.95,-1.4) 28(2.95,-1) 29(2.95,-0.6) 30(2.95,-0.2) 31(2.95,0.2) 32(2.95,0.6) 33(2.95,1) 34(2.95,1.4) 35(2.95,1.8) 36(2.95,2.2)
  rrect25% 0.2x0.84 smd mask+0: 13(-2.2,-2.95) 14(-1.8,-2.95) 15(-1.4,-2.95) 16(-1,-2.95) 17(-0.6,-2.95) 18(-0.2,-2.95) 19(0.2,-2.95) 20(0.6,-2.95) 21(1,-2.95) 22(1.4,-2.95) 23(1.8,-2.95) 24(2.2,-2.95) 37(2.2,2.95) 38(1.8,2.95) 39(1.4,2.95) 40(1,2.95) 41(0.6,2.95) 42(0.2,2.95) 43(-0.2,2.95) 44(-0.6,2.95) 45(-1,2.95) 46(-1.4,2.95) 47(-1.8,2.95) 48(-2.2,2.95)
  rect 3.1x3.1 smd paste-3.1 mask+0: 49(0,0)
QFN40P700X700X80-57T560X560N [mm] "Quad Flat No-Lead (QFN with Tab), 0.40 mm pitch; square, 14 pin X 14 pin, 7.00 mm L X 7.00 mm W X 0.80 mm H body"
  rrect50% 0.86x0.2 smd mask+0: 1(-3.43,2.6) 2(-3.43,2.2) 3(-3.43,1.8) 4(-3.43,1.4) 5(-3.43,1) 6(-3.43,0.6) 7(-3.43,0.2) 8(-3.43,-0.2) 9(-3.43,-0.6) 10(-3.43,-1) 11(-3.43,-1.4) 12(-3.43,-1.8) 13(-3.43,-2.2) 14(-3.43,-2.6) 29(3.43,-2.6) 30(3.43,-2.2) 31(3.43,-1.8) 32(3.43,-1.4) 33(3.43,-1) 34(3.43,-0.6) 35(3.43,-0.2) 36(3.43,0.2) 37(3.43,0.6) 38(3.43,1) 39(3.43,1.4) 40(3.43,1.8) 41(3.43,2.2) 42(3.43,2.6)
  rrect50% 0.2x0.86 smd mask+0: 15(-2.6,-3.43) 16(-2.2,-3.43) 17(-1.8,-3.43) 18(-1.4,-3.43) 19(-1,-3.43) 20(-0.6,-3.43) 21(-0.2,-3.43) 22(0.2,-3.43) 23(0.6,-3.43) 24(1,-3.43) 25(1.4,-3.43) 26(1.8,-3.43) 27(2.2,-3.43) 28(2.6,-3.43) 43(2.6,3.43) 44(2.2,3.43) 45(1.8,3.43) 46(1.4,3.43) 47(1,3.43) 48(0.6,3.43) 49(0.2,3.43) 50(-0.2,3.43) 51(-0.6,3.43) 52(-1,3.43) 53(-1.4,3.43) 54(-1.8,3.43) 55(-2.2,3.43) 56(-2.6,3.43)
  rect 4.9x4.9 smd paste-4.9 mask+0: 57(0,0)
QFN50P320X250X90-15T140X210N [mm] "Quad Flat No-Lead (QFN with Tab), 0.50 mm pitch; rect., 4 pin X 3 pin, 3.20 mm L X 2.50 mm W X 0.90 mm H body"
  rrect25% 0.7x0.27 smd mask+0: 1(-1.25,0.75) 2(-1.25,0.25) 3(-1.25,-0.25) 4(-1.25,-0.75) 8(1.25,-0.75) 9(1.25,-0.25) 10(1.25,0.25) 11(1.25,0.75)
  rrect25% 0.27x0.7 smd mask+0: 5(-0.5,-1.6) 6(0,-1.6) 7(0.5,-1.6) 12(0.5,1.6) 13(0,1.6) 14(-0.5,1.6)
  rect 1.4x2.1 smd paste-2.1 mask+0: 15(0,0)
QFN50P600X600X100-37AN [mm]
  rrect50% 1.1x0.3 smd mask+0: 1(-2.8,2) 2(-2.8,1.5) 3(-2.8,1) 4(-2.8,0.5) 5(-2.8,0) 6(-2.8,-0.5) 7(-2.8,-1) 8(-2.8,-1.5) 9(-2.8,-2) 19(2.8,-2) 20(2.8,-1.5) 21(2.8,-1) 22(2.8,-0.5) 23(2.8,0) 24(2.8,0.5) 25(2.8,1) 26(2.8,1.5) 27(2.8,2)
  rrect50% 0.3x1.1 smd mask+0: 10(-2,-2.8) 11(-1.5,-2.8) 12(-1,-2.8) 13(-0.5,-2.8) 14(0,-2.8) 15(0.5,-2.8) 16(1,-2.8) 17(1.5,-2.8) 18(2,-2.8) 28(2,2.8) 29(1.5,2.8) 30(1,2.8) 31(0.5,2.8) 32(0,2.8) 33(-0.5,2.8) 34(-1,2.8) 35(-1.5,2.8) 36(-2,2.8)
  rect 3.8x3.8 smd: 37(0,0)
QFN_MPS_MP2316 [mm]
  rect 0.75x0.25 smd mask+0: 1(-0.8,1)
  rect 0.7x0.25 smd mask+0: 2(-0.8,0.5) 3(-0.8,0) 4(-0.8,-0.5) 5(-0.8,-1) 7(0.8,-1) 8(0.8,-0.5) 9(0.8,0) 10(0.8,0.5) 11(0.8,1)
  rect 0.25x0.7 smd mask+0: 6(0,-1.45) 12(0,1.45)
  rect 0.35x0.25 smd mask+0: 13(0,0.5) 14(0,0)
RESC1005X40N#1 [mm]
  rect 0.57x0.62 smd mask+0: 1(-0.48,0) 2(0.48,0)
RESC1005X40N#2 [mm]
  rrect25% 0.57x0.62 smd mask+0: 1(-0.48,0) 2(0.48,0)
RESC1609X55N [mm]
  rect 0.9x1 smd mask+0: 1(-0.8,0) 2(0.8,0)
RESC2013X70N [mm]
  rect 1.05x1.4 smd: 1(-0.95,0) 2(0.95,0)
RESC3225X60N [mm]
  rect 1.1x2.7 smd: 1(-1.5,0) 2(1.5,0)
SAMTEC_FTSH-105-01-F-DV [mil]
  rect 110x29 smd: 1(-80,100) 2(80,100) 3(-80,50) 4(80,50) 5(-80,0) 6(80,0) 7(-80,-50) 8(80,-50) 9(-80,-100) 10(80,-100)
SAMTEC_SMM-110-02-F-S [mm]
  rect 0.8x2.35 smd: 1(-9,-1.425) 2(-7,1.425) 3(-5,-1.425) 4(-3,1.425) 5(-1,-1.425) 6(1,1.425) 7(3,-1.425) 8(5,1.425) 9(7,-1.425) 10(9,1.425)
SOD3716X135N [mm]
  rect 1x0.8 smd: A(1.8,0) K(-1.8,0)
SODFL1006X43AN12 [mm]
  rect 0.43x0.32 smd: 1(-0.55,0) 2(0.55,0)
SODFL1006X43N12 [mm]
  rect 0.32x0.43 smd: 1(-0.55,0) 2(0.55,0)
SODFL2513X80N [mm]
  rrect25% 0.97x0.57 smd: A(1.07,0)
  rrect25% 0.97x0.6 smd: K(-1.07,0)
SOIC127P600X175-8N [mm]
  rect 1.97x0.6 smd mask+0: 1(-2.47,1.915) 2(-2.47,0.645) 3(-2.47,-0.625) 4(-2.47,-1.895) 5(2.47,-1.895) 6(2.47,-0.625) 7(2.47,0.645) 8(2.47,1.915)
SON50P120X160X60-5T55X91N [mm] "Small Outline No-Lead (SON with Tab), 0.50 mm pitch; 4 pin, 1.20 mm L X 1.60 mm W X 0.60 mm H body"
  rrect52% 0.67x0.27 smd mask+0: 1(-0.81,0.25) 2(-0.81,-0.25) 3(0.81,-0.25) 4(0.81,0.25)
  rect 0.55x0.91 smd paste-0.099 mask+0: 5(0,0)
SON50P250X100X50-10N [mm] "Small Outline No-Lead (SON), 0.50 mm pitch; 10 pin, 2.50 mm L X 1.00 mm W X 0.50 mm H body"
  rrect55% 0.7x0.22 smd mask+0: 1(-0.505,1) 2(-0.5,0.5) 3(-0.5,0) 4(-0.5,-0.5) 5(-0.5,-1) 6(0.5,-1) 7(0.5,-0.5) 8(0.5,0) 9(0.5,0.5) 10(0.5,1)
SON95P300X300X80-7N [mm]
  rect 0.4x1 smd: 1(-0.95,-1.4) 2(0,-1.4) 3(0.95,-1.4) 4(0.95,1.4) 5(0,1.4) 6(-0.95,1.4)
  rect 2x1.3 smd: 7(0,0)
SOT65P210X100-3AN [mm]
  rect 0.5x1 smd: 1(-0.65,-1.1) 2(0.65,-1.1) 3(0,1.1)
SOT65P210X110-6N [mm]
  rect 0.95x0.4 smd mask+0: 1(-1.1,0.65) 2(-1.1,0) 3(-1.1,-0.65) 4(1.1,-0.65) 5(1.1,0) 6(1.1,0.65)
SOT95P240X110-3N [mm]
  rrect50% 1.16x0.6 smd: 1(-1.03,0.95) 2(-1.03,-0.95) 3(1.03,0)
SOT95P240X110_GSD-3N [mm]
  rect 0.65x1.05 smd: D(0,1.15) G(-0.95,-1.15) S(0.95,-1.15)
SOT95P280X145-5N [mm]
  rrect50% 1.36x0.6 smd: 1(-1.18,0.95) 2(-1.18,0) 3(-1.18,-0.95) 4(1.18,-0.95) 5(1.18,0.95)
SOTFL50P160X60-6N [mm]
  rrect53% 0.56x0.3 smd mask+0: 1(-0.78,0.5) 2(-0.78,0) 3(-0.78,-0.5) 4(0.78,-0.5) 5(0.78,0) 6(0.78,0.5)
SOTFL50P160X80_GSD-3N [mm]
  rect 0.4x0.77 smd: D(0,0.69) G(-0.5,-0.69) S(0.5,-0.69)
SW_KSC221J [mm]
  rect 1x2.8 smd: 1(2,2.9) 2(2,-2.9) 3(-2,2.9) 4(-2,-2.9)
SW_TDA02 [mm]
  rect 1.27x0.76 smd: 1(-3.81,0.635) 2(-3.81,-0.635) 3(3.81,-0.635) 4(3.81,0.635)
TC_TC2050-IDC-NL#1 [mil]
  round 31 smd paste-50: 1(-100,-25) 2(-50,-25) 3(0,-25) 4(50,-25) 5(100,-25) 6(100,25) 7(50,25) 8(0,25) 9(-50,25) 10(-100,25)
  round 59 hole 39 unplated mask+0: MT1(-150,0) MT2(150,40) MT3(150,-40)
TC_TC2050-IDC-NL#2 [mil]
  round 31 smd paste-50: 1(-100,-25) 2(-50,-25) 3(0,-25) 4(50,-25) 5(100,-25) 6(100,25) 7(50,25) 8(0,25) 9(-50,25) 10(-100,25)
  round 0 hole 39 unplated mask+0: MT1(-150,0) MT2(150,40) MT3(150,-40)
TE_640456-2 [mm] "CONN HEADER VERT 2POS .100 TIN"
  round 1.5 hole 1.02: 1(-1.27,0) 2(1.27,0)
TP0762 [mil] "30mil SMT Round Testpoint"
  round 30 smd paste-100: 1(0,0)
XMULTIPLE_XMG-J1B211 [mil]
  rect 60x60 hole 35: 1(0,0)
  round 60 hole 35: 2(50,-100) 3(100,0) 4(150,-100) 5(200,0) 6(250,-100) 7(300,0) 8(350,-100) 9(400,0) 10(450,-100)
  round 76 hole 47.24: D1(-36.61,-510) D2(63.78,-510) D3(386.61,-510) D4(487.01,-510)
  round 127.95 hole 127.95 unplated: MNT1(0,-350) MNT2(450,-350)
  round 100 hole 63: SHLD1(-84.25,-230) SHLD2(534.25,-230)
XTAL_C3E-3427 [mm]
  rect 1.4x1.15 smd: 1(-1.1,-0.8) 2(1.1,-0.8) 3(1.1,0.8) 4(-1.1,0.8)

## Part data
C1 C7 C19 C20 C21 C155 C159: library part 1001196, "CAP TANT 100UF 6.3V 20% 1206"
C2 C6 C27 C47 C54 C65 C72 C85 C87 C90 C103 C104 C106 C120 C124 C149 C154 C158: library part 1001168, "CAP CER 10UF 10V 20% X5R 0402"
C3 C50 C52 C53 C68 C70 C71 C83 C84 C121 C122 C123 C125 C126 C127 C128 C129 C131 C132 C147: library part 1001167, "CAP CER 1UF 10V 10% X5R 0402"
C4 C34 C35 C36 C79 C109 C110 C111: library part 1000073, "CAP CER 1UF 6.3V 20% X5R 0402"
C5 C143: library part 1001303, "CAP CER 2.2UF 16V 10% X5R 0603"
C8 C11 C156 C160: library part 1000998, "CAP CER 22UF 10V 20% X5R 0603"
C9 C13 C22 C23 C24 C25 C26 C28 C29 C30 C31 C32 C33 C38 C39 C40 C44 C45 C48 C49 C51 C55 C56 C57 C62 C63 C66 C67 C69 C73 C74 C75 C78 C80 C86 C88 C91 C92 C93 C94 C95 C96 C97 C98 C99 C100 C105 C107 C108 C139 C140 C145 C146 C148 C157 C161: library part 1000006, "CAP 100nF 16V 10% X7R 0402"
C10: library part 1000501, "CAP CER 47UF 6.3V 20% X5R 0805"
C12 C46 C64 C118 C119 C150 C151 C152 C153: library part 1000918, "CAP CER 0.1UF 50V 10% X7R 0402"
C14: library part 1000007, "CAP 47pF 50V 5% NP0 0402"
C15 C16 C17 C18: library part 1000111, "CAP CER 10UF 16V 10% X5R 0805"
C37: library part 1000566, "CAP CER 100UF 10V 20% X5R 1206"
C41 C89 C133 C134: library part 1000067, "CAP CER 1000PF 50V 10% X7R 0402"
C42 C43 C60 C61: library part 1001166, "CAP CER 22PF 50V 5% NP0 0402"
C58 C59 C76 C77: library part 1001883, "CAP CER 0.22UF 6.3V X7R 0402"
C81 C82: library part 1002646, "CAP CER 33PF 50V C0G/NP0 0402"
C101 C102 C130: library part 1000970, "CAP CER 2.2UF 6.3V 20% X5R 0402"
C112 C113 C114 C115 C116 C117: library part 1001541, "CAP CER 10PF 50V 5% NP0 0402"
C135: library part 1000110, "CAP CER 1UF 25V 10% X5R 0603"
C136 C142: library part 1000512, "CAP CER 0.015UF 16V 10% X7R 0402"
C137 C138: library part 1000963, "220nF, 10V, 20%, 0201"
C162: library part 1000463, "CAP CER 4.7UF 4V 20% X5R 0402"
CAD1 CAD2: library part CAD0066, "CBL PLUG-OF-NAILS 10-PIN"
D1 D9 D10: library part 1002593, "TVS DIODE 5.5V 4V 10DFN"
D2: library part 1001264, "TVS DIODE 5VWM SOD923"
D3: library part 1001494, "DIODE ZENER 5.1V 500MW SOD123"
D4: library part 1000794, "DIODE SCHOTTKY 30V 200MA SOT323"
D5 D11: library part 1001189, "LED GREEN 573NM 1208 SMD"
D6 D7: library part 1001637, "TVS DIODE 3.3VWM SOD923"
D8: library part 1000231, "DIODE SCHOTTKY 40V 1A SOD123"
D12: library part 1001188, "LED YELLOW 588NM 1208 SMD"
D13: library part 1002592, "DIODE SCHOTTKY 30V 30MA SMINI2"
D14: library part 1002782, "SMDIO,TVS UNI-DIR 5V 600W SMA"
FIDUCIAL1 FIDUCIAL2 FIDUCIAL3 FIDUCIAL4 FIDUCIAL5 FIDUCIAL6 FIDUCIAL7 FIDUCIAL8 FIDUCIAL9 FIDUCIAL10 FIDUCIAL11 FIDUCIAL12: library part CAD0023, "40 Mil Round Fiducial"
FIL1: library part 1002768, "CAP FEEDTHRU 4.7UF 20% 10V 0805"
H1 H2 H3 H4: library part CAD0006, "NPTH for Tooling, 0.125in dia."
J2 J3 J6: library part 1001136, "CONN HEADER 2POS 1.25MM VERT TIN"
J4: library part 1001105, "DC Power Jack"
J5: library part 1002003, "CONN HEADER VERT 2POS .100 TIN"
J7: library part 1001130, "SMCONN,MINI PCI EXP, 6.8MM HT"
J8: library part 1001120, "MEMORY CARD 6POS PUSH/PULL SMD"
J9: library part 1000034, "CONN HEADER 10POS DUAL .05\" SMD"
J10: library part 1001118, "CONN TRANSFLSH R/A PUSH-PUSH SMD"
J11: library part 1001137, "CONN HEADER 4POS 1.25MM VERT TIN"
J12 J13: library part 1002612, "CONN MAGJACK 1PORT 1000 BASE-T IND"
J14 J16: library part 1001132, "CONN HEADER 20POS 1.25MM R/A SMD"
J15: library part 1001866, "CONN FFC FPC VERT 15POS 1MM SMD"
J17: library part 1001145, "CONN FPC 20POS 0.5MM PITCH SMD"
J18: library part 1001121, "USB Stacked Dual A type"
J19: library part 1002675, "USB 3.1 SHIELDED I/O RECP TYPE C GEN2"
J20 J27: library part 1002698, "CONN HEADER 40POS .100 PRESS-FIT"
J21: library part 1002596, "CONN JACK STEREO 3.5MM R/A"
J22 J23: library part 1001495, "CONN RCPT 2MM 10POS SMD"
J28: library part 1001117, "CONN RECEPT MICRO-USB TYPE AB R/A"
L1: library part 1001912, "FIXED IND 1.5UH 4.5A 42 MOHM SMD"
L2 L4 L5 L7: library part 1001175, "FERRITE BEAD 120 OHM .35A 0402"
L3 L6: library part 1002610, "FIXED IND 4.7UH 1.1A 110 MOHM"
L8 L13 L14 L15 L22 L23 L29 L30 L36 L37 L39: library part 1001174, "FERRITE BEAD 220 OHM 2.0A 0805"
L9 L10 L11 L12 L38: library part 1001173, "CHOKE COM MODE 120 OHM .37A"
L16 L17 L18 L19 L20 L21: library part 1002041, "FERRITE BEAD 1.8 KOHM 0402 1LN"
L24 L25 L26 L27 L28 L31 L32 L33 L34 L35: library part 1001014, "CHOKE COIL COMMON MODE 150MA SMD"
NT1: library part CAD0044, "NET TIE FOR I.MX6x SOM"
Q1 Q2 Q3 Q4 Q5 Q8 Q13 Q14: library part 1000715, "MOSFET N-CH 60V 115MA SOT-523F"
Q6 Q9 Q10 Q11 Q12: library part 1000306, "MOSFET N-CH 30V 500MA SOT-23"
Q7: library part 1001204, "TRANS GP SS PNP 40V SOT23"
R1 R22 R31 R214 R255: library part 1001557, "RES 0.0 OHM 1/8W JUMP 0805 SMD"
R2 R3 R4 R5 R6 R7 R8 R9 R11 R13 R14 R18 R28 R29 R34 R45 R56 R57 R65 R66 R67 R68 R76 R77 R78 R79 R155 R156 R157 R158 R164 R165 R173 R174 R175 R176 R177 R178 R185 R186 R187 R188 R189 R190 R191 R192 R196 R197 R205 R213 R221 R222 R223 R224 R225 R226 R227 R228 R229 R230 R231 R232 R233 R234 R238 R239 R240 R241 R242 R243 R245 R246 R247 R248 R249 R250 R252 R254 R256 R257: library part 1000076, "RES 0.0 OHM 1/10W 0402 SMD"
R10 R12 R16 R20 R21 R51 R52 R55 R70 R74 R75 R80 R86 R87 R88 R89 R90 R91 R92 R93 R94 R95 R96 R97 R98 R99 R100 R101 R106 R107 R118 R119 R120 R121 R122 R123 R124 R125 R126 R127 R128 R129 R130 R131 R132 R133 R134 R137 R142 R143 R145 R147 R148 R154 R163 R169 R193 R198 R215 R235 R244 R251 R253: library part 1000537, "RES 10.0K OHM 1/10W 1% 0402 SMD"
R15: library part 1001313, "RES 51K OHM 1/10W 5% 0402 SMD"
R17 R33 R37 R39 R40 R46 R47 R54 R69 R108 R109 R144 R153 R168 R194 R216 R259 R260: library part 1000480, "RES 100K OHM 1/10W 1% 0402 SMD"
R19: library part 1001323, "RES 270 OHM 1/2W 5% 0805 SMD"
R23 R59 R61 R72 R73 R104 R105 R151: library part 1000079, "RES 1.00K OHM 1/10W 1% 0402 SMD"
R24 R43 R44: library part 1000701, "RES 470K OHM 1/10W 1% 0402 SMD"
R25 R162: library part 1001917, "RES SMD 2.2M OHM 5% 1/10W 0402"
R26 R50 R102 R103: library part 1001200, "RES 12.0K OHM 1/10W 1% 0603 SMD"
R27: library part 1000142, "RES 20K OHM 1/10W 5% 0603 SMD"
R30 R112 R117 R195 R217 R218: library part 1000466, "RES 49.9 OHM 1/10W 1% 0402 SMD"
R32 R35 R36 R38 R81 R113: library part 1000038, "RES 4.7K OHM 1/10W 5% 0402 SMD"
R41 R71 R146 R170 R199 R219 R220: library part 1000208, "RES 0.0 OHM 1/10W 0603"
R42: library part 1001154, "RES 220 OHM 1/16W 1% 0402 SMD"
R48: library part 1001916, "RES SMD 2 OHM 5% 1/10W 0603"
R49: library part 1001518, "RES 53.6K OHM 1/10W 1% 0603 SMD"
R53 R152: library part 1001149, "RES 22.1K OHM 1/16W 1% 0402 SMD"
R58 R64 R160 R161 R166 R167: library part 1000467, "RES 100 OHM 1/10W 1% 0402 SMD"
R60 R62 R63 R203 R204: library part 1001158, "RES 120 OHM 1/16W 1% 0402 SMD"
R82 R114: library part 1000469, "RES 2.37K OHM 1/10W 1% 0402 SMD"
R83 R84 R115 R116: library part 1000465, "RES 150 OHM 1/10W 1% 0402 SMD"
R85: library part 1000229, "RES 0.0 OHM 1/2W 1210 SMD"
R110 R111 R236 R237: library part 1000601, "RES 22.0 OHM 1/10W 1% 0402 SMD"
R135: library part 1000971, "RES 1.00M OHM 1/16W 1% 0402 SMD"
R136 R138 R139 R140 R149 R258: library part 1001155, "RES 47.0K OHM 1/16W 1% 0402 SMD"
R141: library part 1000828, "RES 12.1K OHM 1/10W 1% 0402 SMD"
R150: library part 1000170, "RES 52.3K OHM 1/10W 1% 0402 SMD"
R159 R171 R172 R179 R180 R181 R182 R183 R184: library part 1001156, "RES 2.20K OHM 1/16W 1% 0402 SMD"
S2: library part 1001500, "SWITCH DIP 2POS HALF PITCH 24V"
SW1 SW2: library part 1001124, "SWITCH TACTILE SPST-NO 0.05A 32V"
TP1 TP2 TP3 TP4 TP5 TP6 TP7 TP8 TP9 TP10 TP13 TP14 TP15 TP16 TP18 TP19 TP20 TP21: library part CAD0011, "TEST POINT 30MIL PAD SMT"
U1: library part 1002581, "ConnectCore for i.MX8X module - LGA"
U2 U32 U33: library part 1001857, "IC SW W/CTRL SLEW RATE 4TDFN"
U3: library part 1001907, "IC REG BUCK ADJ 3A SYNC"
U4 U5: library part 1001179, "IC SWITCH SPDT SC88"
U6 U7: library part 1002681, "IC CAN TRANSEIVER HS 8SOIC"
U8: library part 1001420, "IC TRANSCEIVER RS485 8-SOIC"
U9 U22: library part 1001009, "MOSFET DL N-CH 60V 410MA SOT-563"
U10: library part 1002531, "IC BUS TRANSCVR TRI-ST DL 10UQFN"
U11 U12: library part 1002583, "IC TRANSCEIVER ETHERNET 48-QFN"
U13: library part 1001114, "4-PORT USB 2.0 HUB CTRLR 36VQFN"
U14 U31: library part 1001143, "IC SW DISTRIBUTION 2CHAN 8SOIC"
U15 U16: library part 1001265, "TVS DIODE 5.5VWM 6SON"
U17: library part 1002584, "IC DIFF SWITCH 2:1 HUQFN16"
U18: library part 1002585, "IC USB PD TCPC PHY HX2QFN16"
U19: library part 1002586, "IC USB POWER SWITCH 16WLCSP"
U20: library part 1002001, "IC CODEC AUDIO FLEXSOUND 56TQFN"
U21 U23 U24 U25: library part 1001163, "MOSFET P-CH 20V 3.7A SOT23-3"
U26: library part 1001972, "MOSFET P-CH 12V 12A 6QFN"
U27: library part 1001979, "IC REG LDO ADJ 0.15A SOT25"
U28: library part 1002449, "SMIC PCIE CLOCK GEN 100MHZ 14QFN"
U29: library part 1002597, "IC TRANSLATING TXRX 8XSON"
X1 X2: library part 1001497, "SMCRY,25MHZ 50PPM 20PF RH100 EXT"
X3: library part 1001134, "CRYSTAL 24MHZ 18PF SMD"

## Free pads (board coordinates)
  round 5.5 hole 3.2: 0(43.4,25.3) 0(43.4,56.6) 0(96.4,20.225) 0(96.4,61.9) TOOL1(3,3) TOOL2(97,3) TOOL3(97,69) TOOL4(3,69)
  round 5.5 hole 2.6: 0(66,17.35) 0(90.2,17.35)
  round 0 on Mech32767 paste+0 mask+0: 1(72.9,62.296) 1(72.9,62.296) 1(72.9,62.296) 1(72.9,62.296)

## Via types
v1: diameter 0.45, hole 0.2, Top to Bottom, tented both sides, 1412 vias

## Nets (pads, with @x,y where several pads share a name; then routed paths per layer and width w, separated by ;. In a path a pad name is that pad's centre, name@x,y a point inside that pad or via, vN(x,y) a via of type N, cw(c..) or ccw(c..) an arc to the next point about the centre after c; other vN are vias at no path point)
1V8: C158.2 U1.AH1 U1.AH2 U1.AH3 U33.3 | length 67.5
  Top w0.3: v1(22.075,67.775) 22.825,68.525 26.256,68.525 27.687,69.956 30.551,69.956 33.759,66.748 35.748,66.748 37.04,68.04 41.286,68.04 41.725,67.601 42.485,67.601 42.779,67.895 42.779,68.311 42.704,68.386 42.704,68.854 43.075,69.225 45.075,69.225 45.85,68.45 60.05,68.45 61.322,67.178 v1(61.428,67.178) ; U1.AH3@54.78,55.74 54.802,55.762 54.802,56.988 U1.AH2@54.78,57.01 U1.AH1@54.78,58.28 54.877,58.377 54.877,59.302 v1(55,59.425)
  Bottom w0.25: v1@22.087,67.763 21.075,66.75 21.075,66.15 21.675,65.55 21.675,64.053 21.879,63.849 21.879,63.521 22.45,62.95 C158.2@22.965,62.95 22.965,63.46 22.59,63.835 U33.3@22.59,64.1
  Bottom w0.3: v1(55,59.425) 55.975,59.425 57.375,60.825 57.375,61.825 58.25,62.7 58.25,63.9 58.875,64.525 59.975,64.525 61.428,65.978 v1(61.428,67.178)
